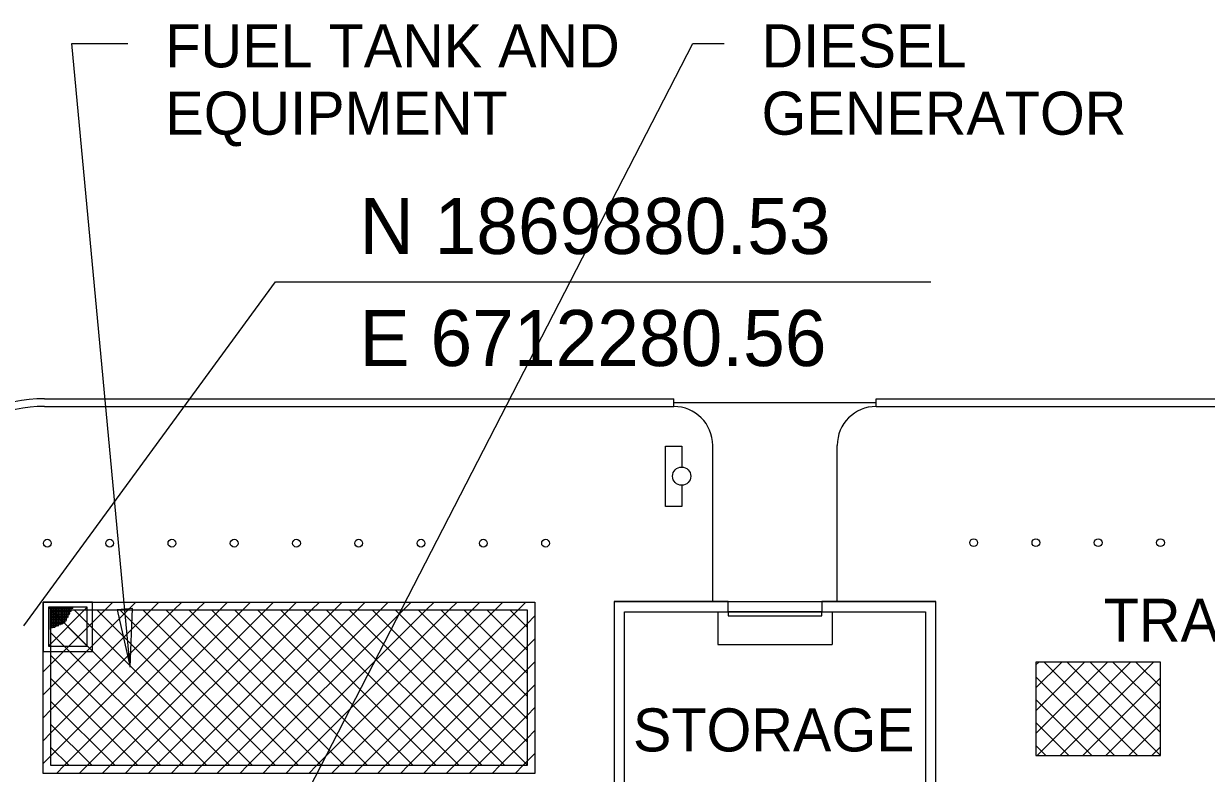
# Model space of a CAD drawing. Extents: x 6712138 to 6712574, y 1869536 to 1870160.
# Drawn here: x 6712280.5 to 6712356.5, y 1869871 to 1869919.2 of the extents above; entities that cross this region are included whole.
import ezdxf

# ---------------------------------------------------------------- set-up
doc = ezdxf.new("R2010")
doc.units = 0
for name, color, linetype in [('A-ANNO-TEXT', 7, 'Continuous'), ('A-DETL-GENF', 7, 'Continuous'), ('A-DETL-MBND', 7, 'Continuous'), ('C-PRKG-CONC', 7, 'Continuous'), ('C-PRKG-STRP', 7, 'Continuous'), ('C-SIGN-PARKING', 7, 'Continuous'), ('G-DETL-LW02', 7, 'Continuous'), ('I-FURN', 7, 'Continuous'), ('I-WALL', 7, 'Continuous'), ('M-Plan-Misc', 7, 'Continuous')]:
    doc.layers.add(name, color=color, linetype=linetype)

msp = doc.modelspace()

# ---------------------------------------------------------------- linework, layer by layer
at = {"layer": 'A-ANNO-TEXT'}
for p, q in [((6712283.645, 1869917.929), (6712287.243, 1869917.929)), ((6712287.387, 1869877.857), (6712283.645, 1869917.929)), ((6712283.645, 1869917.929), (6712287.243, 1869917.929)), ((6712287.387, 1869877.857), (6712283.645, 1869917.929)), ((6712293.94, 1869860.435), (6712323.513, 1869917.929)), ((6712293.94, 1869860.435), (6712323.513, 1869917.929)), ((6712323.513, 1869917.929), (6712325.537, 1869917.929)), ((6712323.513, 1869917.929), (6712325.537, 1869917.929)), ((6712287.53, 1869881.637), (6712286.547, 1869881.545)), ((6712287.53, 1869881.637), (6712286.547, 1869881.545)), ((6712287.53, 1869881.637), (6712286.547, 1869881.545)), ((6712287.53, 1869881.637), (6712286.547, 1869881.545)), ((6712286.547, 1869881.545), (6712287.387, 1869877.857)), ((6712286.547, 1869881.545), (6712287.387, 1869877.857)), ((6712286.547, 1869881.545), (6712287.387, 1869877.857)), ((6712286.547, 1869881.545), (6712287.387, 1869877.857)), ((6712287.387, 1869877.857), (6712287.53, 1869881.637)), ((6712287.387, 1869877.857), (6712287.53, 1869881.637)), ((6712287.387, 1869877.857), (6712287.53, 1869881.637)), ((6712287.387, 1869877.857), (6712287.53, 1869881.637))]:
    msp.add_line(p, q, dxfattribs=at)
at = {"layer": 'A-DETL-GENF'}
for p, q in [((6712282.297, 1869878.058), (6712285.778, 1869881.538)), ((6712282.297, 1869876.585), (6712287.251, 1869881.538)), ((6712282.297, 1869873.638), (6712290.197, 1869881.538)), ((6712282.297, 1869872.165), (6712291.671, 1869881.538)), ((6712282.297, 1869873.638), (6712290.197, 1869881.538)), ((6712282.297, 1869872.165), (6712291.671, 1869881.538)), ((6712282.297, 1869878.058), (6712285.778, 1869881.538)), ((6712282.297, 1869876.585), (6712287.251, 1869881.538)), ((6712282.297, 1869875.111), (6712288.724, 1869881.538)), ((6712292.304, 1869871.538), (6712282.304, 1869881.538)), ((6712283.144, 1869871.538), (6712293.144, 1869881.538)), ((6712283.144, 1869871.538), (6712293.144, 1869881.538)), ((6712293.777, 1869871.538), (6712283.777, 1869881.538)), ((6712284.617, 1869871.538), (6712294.617, 1869881.538)), ((6712284.617, 1869871.538), (6712294.617, 1869881.538)), ((6712295.25, 1869871.538), (6712285.25, 1869881.538)), ((6712285.778, 1869881.538), (6712286.278, 1869882.038)), ((6712286.09, 1869871.538), (6712296.09, 1869881.538)), ((6712286.09, 1869871.538), (6712296.09, 1869881.538)), ((6712296.723, 1869871.538), (6712286.723, 1869881.538)), ((6712287.251, 1869881.538), (6712287.751, 1869882.038)), ((6712287.563, 1869871.538), (6712297.563, 1869881.538)), ((6712287.563, 1869871.538), (6712297.563, 1869881.538)), ((6712298.196, 1869871.538), (6712288.196, 1869881.538)), ((6712288.724, 1869881.538), (6712289.224, 1869882.038)), ((6712289.036, 1869871.538), (6712299.036, 1869881.538)), ((6712289.036, 1869871.538), (6712299.036, 1869881.538)), ((6712299.67, 1869871.538), (6712289.67, 1869881.538)), ((6712290.197, 1869881.538), (6712290.697, 1869882.038)), ((6712290.509, 1869871.538), (6712300.509, 1869881.538)), ((6712290.509, 1869871.538), (6712300.509, 1869881.538)), ((6712301.143, 1869871.538), (6712291.143, 1869881.538)), ((6712291.671, 1869881.538), (6712292.171, 1869882.038)), ((6712291.983, 1869871.538), (6712301.983, 1869881.538)), ((6712291.983, 1869871.538), (6712301.983, 1869881.538)), ((6712302.616, 1869871.538), (6712292.616, 1869881.538)), ((6712293.144, 1869881.538), (6712293.644, 1869882.038)), ((6712293.456, 1869871.538), (6712303.456, 1869881.538)), ((6712293.456, 1869871.538), (6712303.456, 1869881.538)), ((6712304.089, 1869871.538), (6712294.089, 1869881.538)), ((6712294.617, 1869881.538), (6712295.117, 1869882.038)), ((6712294.929, 1869871.538), (6712304.929, 1869881.538)), ((6712294.929, 1869871.538), (6712304.929, 1869881.538)), ((6712305.562, 1869871.538), (6712295.562, 1869881.538)), ((6712296.09, 1869881.538), (6712296.59, 1869882.038)), ((6712296.402, 1869871.538), (6712306.402, 1869881.538)), ((6712296.402, 1869871.538), (6712306.402, 1869881.538)), ((6712307.035, 1869871.538), (6712297.035, 1869881.538)), ((6712297.563, 1869881.538), (6712298.063, 1869882.038)), ((6712297.875, 1869871.538), (6712307.875, 1869881.538)), ((6712297.875, 1869871.538), (6712307.875, 1869881.538)), ((6712308.508, 1869871.538), (6712298.508, 1869881.538)), ((6712299.036, 1869881.538), (6712299.536, 1869882.038)), ((6712299.348, 1869871.538), (6712309.348, 1869881.538)), ((6712299.348, 1869871.538), (6712309.348, 1869881.538)), ((6712309.981, 1869871.538), (6712299.981, 1869881.538)), ((6712300.509, 1869881.538), (6712301.009, 1869882.038)), ((6712300.821, 1869871.538), (6712310.821, 1869881.538)), ((6712300.821, 1869871.538), (6712310.821, 1869881.538)), ((6712311.455, 1869871.538), (6712301.455, 1869881.538)), ((6712301.983, 1869881.538), (6712302.483, 1869882.038)), ((6712302.295, 1869871.538), (6712312.295, 1869881.538)), ((6712302.295, 1869871.538), (6712312.295, 1869881.538)), ((6712312.881, 1869871.585), (6712302.928, 1869881.538)), ((6712303.456, 1869881.538), (6712303.956, 1869882.038)), ((6712312.881, 1869873.059), (6712304.401, 1869881.538)), ((6712304.929, 1869881.538), (6712305.429, 1869882.038)), ((6712312.881, 1869874.532), (6712305.874, 1869881.538)), ((6712306.402, 1869881.538), (6712306.902, 1869882.038)), ((6712312.881, 1869876.005), (6712307.347, 1869881.538)), ((6712307.875, 1869881.538), (6712308.375, 1869882.038)), ((6712312.881, 1869877.478), (6712308.82, 1869881.538)), ((6712309.348, 1869881.538), (6712309.848, 1869882.038)), ((6712312.881, 1869878.951), (6712310.293, 1869881.538)), ((6712310.821, 1869881.538), (6712311.321, 1869882.038)), ((6712312.881, 1869880.424), (6712311.767, 1869881.538)), ((6712312.295, 1869881.538), (6712312.795, 1869882.038)), ((6712318.464, 1869882.073), (6712318.464, 1869856.073)), ((6712325.797, 1869882.073), (6712318.464, 1869882.073)), ((6712319.131, 1869856.739), (6712319.131, 1869881.406)), ((6712319.131, 1869881.406), (6712325.797, 1869881.406)), ((6712325.797, 1869881.406), (6712325.797, 1869882.073)), ((6712339.131, 1869882.073), (6712331.797, 1869882.073)), ((6712331.797, 1869882.073), (6712331.797, 1869881.406)), ((6712331.797, 1869881.406), (6712338.464, 1869881.406)), ((6712338.464, 1869881.406), (6712338.464, 1869856.739)), ((6712339.131, 1869856.073), (6712339.131, 1869882.073)), ((6712303.768, 1869871.538), (6712312.881, 1869880.651)), ((6712303.768, 1869871.538), (6712312.881, 1869880.651)), ((6712312.881, 1869880.651), (6712313.381, 1869881.151)), ((6712290.831, 1869871.538), (6712282.297, 1869880.072)), ((6712305.241, 1869871.538), (6712312.881, 1869879.178)), ((6712305.241, 1869871.538), (6712312.881, 1869879.178)), ((6712312.881, 1869879.178), (6712313.381, 1869879.678)), ((6712289.358, 1869871.538), (6712282.297, 1869878.599)), ((6712281.797, 1869877.558), (6712282.297, 1869878.058)), ((6712306.714, 1869871.538), (6712312.881, 1869877.705)), ((6712312.881, 1869877.705), (6712313.381, 1869878.205)), ((6712345.557, 1869876.534), (6712347.212, 1869878.189)), ((6712345.557, 1869878.007), (6712345.739, 1869878.189)), ((6712345.557, 1869875.061), (6712348.685, 1869878.189)), ((6712345.557, 1869873.588), (6712350.158, 1869878.189)), ((6712345.631, 1869872.189), (6712351.631, 1869878.189)), ((6712352.086, 1869872.189), (6712346.086, 1869878.189)), ((6712347.105, 1869872.189), (6712353.105, 1869878.189)), ((6712347.105, 1869872.189), (6712353.105, 1869878.189)), ((6712353.557, 1869872.191), (6712347.56, 1869878.189)), ((6712353.557, 1869873.664), (6712349.033, 1869878.189)), ((6712353.557, 1869875.138), (6712350.506, 1869878.189)), ((6712353.557, 1869876.611), (6712351.979, 1869878.189)), ((6712287.884, 1869871.538), (6712282.297, 1869877.125)), ((6712350.613, 1869872.189), (6712345.557, 1869877.245)), ((6712348.578, 1869872.189), (6712353.557, 1869877.169)), ((6712281.797, 1869876.085), (6712282.297, 1869876.585)), ((6712308.187, 1869871.538), (6712312.881, 1869876.232)), ((6712312.881, 1869876.232), (6712313.381, 1869876.732)), ((6712286.411, 1869871.538), (6712282.297, 1869875.652)), ((6712349.14, 1869872.189), (6712345.557, 1869875.772)), ((6712349.14, 1869872.189), (6712345.557, 1869875.772)), ((6712350.051, 1869872.189), (6712353.557, 1869875.695)), ((6712281.797, 1869874.611), (6712282.297, 1869875.111)), ((6712309.66, 1869871.538), (6712312.881, 1869874.759)), ((6712312.881, 1869874.759), (6712313.381, 1869875.259)), ((6712284.938, 1869871.538), (6712282.297, 1869874.179)), ((6712312.881, 1869873.286), (6712313.381, 1869873.786)), ((6712347.667, 1869872.189), (6712345.557, 1869874.299)), ((6712351.524, 1869872.189), (6712353.557, 1869874.222)), ((6712281.797, 1869873.138), (6712282.297, 1869873.638)), ((6712311.133, 1869871.538), (6712312.881, 1869873.286)), ((6712283.465, 1869871.538), (6712282.297, 1869872.706)), ((6712312.881, 1869871.813), (6712313.381, 1869872.313)), ((6712346.194, 1869872.189), (6712345.557, 1869872.826)), ((6712352.997, 1869872.189), (6712353.557, 1869872.749)), ((6712281.797, 1869871.665), (6712282.297, 1869872.165)), ((6712282.644, 1869871.038), (6712283.144, 1869871.538)), ((6712282.644, 1869871.038), (6712283.144, 1869871.538)), ((6712284.117, 1869871.038), (6712284.617, 1869871.538)), ((6712284.117, 1869871.038), (6712284.617, 1869871.538)), ((6712285.59, 1869871.038), (6712286.09, 1869871.538)), ((6712285.59, 1869871.038), (6712286.09, 1869871.538)), ((6712287.063, 1869871.038), (6712287.563, 1869871.538)), ((6712287.063, 1869871.038), (6712287.563, 1869871.538)), ((6712288.536, 1869871.038), (6712289.036, 1869871.538)), ((6712288.536, 1869871.038), (6712289.036, 1869871.538)), ((6712290.009, 1869871.038), (6712290.509, 1869871.538)), ((6712290.009, 1869871.038), (6712290.509, 1869871.538)), ((6712291.483, 1869871.038), (6712291.983, 1869871.538)), ((6712291.483, 1869871.038), (6712291.983, 1869871.538)), ((6712292.956, 1869871.038), (6712293.456, 1869871.538)), ((6712292.956, 1869871.038), (6712293.456, 1869871.538)), ((6712294.429, 1869871.038), (6712294.929, 1869871.538)), ((6712294.429, 1869871.038), (6712294.929, 1869871.538)), ((6712295.902, 1869871.038), (6712296.402, 1869871.538)), ((6712295.902, 1869871.038), (6712296.402, 1869871.538)), ((6712297.375, 1869871.038), (6712297.875, 1869871.538)), ((6712297.375, 1869871.038), (6712297.875, 1869871.538)), ((6712298.848, 1869871.038), (6712299.348, 1869871.538)), ((6712298.848, 1869871.038), (6712299.348, 1869871.538)), ((6712300.321, 1869871.038), (6712300.821, 1869871.538)), ((6712300.321, 1869871.038), (6712300.821, 1869871.538)), ((6712301.795, 1869871.038), (6712302.295, 1869871.538)), ((6712301.795, 1869871.038), (6712302.295, 1869871.538)), ((6712303.268, 1869871.038), (6712303.768, 1869871.538)), ((6712303.268, 1869871.038), (6712303.768, 1869871.538)), ((6712304.741, 1869871.038), (6712305.241, 1869871.538)), ((6712304.741, 1869871.038), (6712305.241, 1869871.538)), ((6712306.214, 1869871.038), (6712306.714, 1869871.538)), ((6712306.214, 1869871.038), (6712306.714, 1869871.538)), ((6712307.687, 1869871.038), (6712308.187, 1869871.538)), ((6712307.687, 1869871.038), (6712308.187, 1869871.538)), ((6712309.16, 1869871.038), (6712309.66, 1869871.538)), ((6712309.16, 1869871.038), (6712309.66, 1869871.538)), ((6712310.633, 1869871.038), (6712311.133, 1869871.538)), ((6712310.633, 1869871.038), (6712311.133, 1869871.538)), ((6712312.106, 1869871.038), (6712312.606, 1869871.538)), ((6712312.106, 1869871.038), (6712312.606, 1869871.538)), ((6712312.606, 1869871.538), (6712312.881, 1869871.813))]:
    msp.add_line(p, q, dxfattribs=at)
at = {"layer": 'A-DETL-MBND'}
for p, q in [((6712325.131, 1869881.406), (6712325.131, 1869879.323)), ((6712325.131, 1869881.406), (6712332.464, 1869881.406)), ((6712331.797, 1869881.406), (6712325.797, 1869881.406)), ((6712325.797, 1869881.406), (6712325.797, 1869881.156)), ((6712331.797, 1869881.156), (6712331.797, 1869881.406)), ((6712332.464, 1869881.406), (6712332.464, 1869879.323)), ((6712325.797, 1869881.156), (6712331.797, 1869881.156)), ((6712325.131, 1869879.323), (6712332.464, 1869879.323))]:
    msp.add_line(p, q, dxfattribs=at)
at = {"layer": 'C-PRKG-CONC'}
for p, q in [((6712281.89, 1869895.107), (6712322.297, 1869895.107)), ((6712322.297, 1869894.607), (6712322.297, 1869895.107)), ((6712335.297, 1869894.607), (6712335.297, 1869895.107)), ((6712335.297, 1869895.107), (6712372.34, 1869895.107)), ((6712281.89, 1869894.607), (6712322.297, 1869894.607)), ((6712322.297, 1869894.857), (6712335.297, 1869894.857)), ((6712335.297, 1869894.607), (6712372.34, 1869894.607)), ((6712324.797, 1869882.073), (6712324.797, 1869892.107)), ((6712324.797, 1869882.073), (6712324.797, 1869892.074)), ((6712332.797, 1869882.074), (6712332.797, 1869892.107)), ((6712332.797, 1869882.074), (6712332.797, 1869892.074))]:
    msp.add_line(p, q, dxfattribs=at)
for centre, radius, start, end in [((6712281.89, 1869885.107), 10, 90, 180.00085), ((6712281.89, 1869885.107), 9.5, 90, 180.00085), ((6712322.297, 1869892.107), 2.5, 0, 90), ((6712335.297, 1869892.107), 2.5, 90, 180)]:
    msp.add_arc(centre, radius, start, end, dxfattribs=at)
at = {"layer": 'C-PRKG-STRP'}
msp.add_line((6712318.464, 1869882.073), (6712339.131, 1869882.073), dxfattribs=at)
at = {"layer": 'C-SIGN-PARKING'}
msp.add_lwpolyline([(6712322.807, 1869889.542), (6712322.807, 1869888.19), (6712321.773, 1869888.19), (6712321.773, 1869892.066), (6712322.807, 1869892.066), (6712322.807, 1869890.714)], dxfattribs=at)
msp.add_circle((6712322.807, 1869890.128), 0.586, dxfattribs=at)
at = {"layer": 'G-DETL-LW02'}
for points in [[(6712281.797, 1869882.038), (6712313.381, 1869882.038), (6712313.381, 1869871.038), (6712281.797, 1869871.038)], [(6712282.297, 1869881.538), (6712312.881, 1869881.538), (6712312.881, 1869871.538), (6712282.297, 1869871.538)], [(6712345.557, 1869878.189), (6712345.557, 1869872.189), (6712353.557, 1869872.189), (6712353.557, 1869878.189)]]:
    msp.add_lwpolyline(points, close=True, dxfattribs=at)
at = {"layer": 'I-FURN'}
for centre in [(6712282.064, 1869885.823), (6712286.064, 1869885.823), (6712290.064, 1869885.823), (6712294.064, 1869885.823), (6712298.064, 1869885.823), (6712302.064, 1869885.823), (6712306.064, 1869885.823), (6712310.064, 1869885.823), (6712314.064, 1869885.823), (6712341.557, 1869885.857), (6712345.557, 1869885.857), (6712349.557, 1869885.857), (6712353.557, 1869885.857)]:
    msp.add_circle(centre, 0.25, dxfattribs=at)
at = {"layer": 'I-WALL'}
for points in [[(6712280.558, 1869880.525), (6712296.723, 1869902.604)], [(6712296.723, 1869902.604), (6712338.804, 1869902.604)]]:
    msp.add_lwpolyline(points, dxfattribs=at)
at = {"layer": 'M-Plan-Misc'}
for p, q in [((6712284.631, 1869881.705), (6712282.131, 1869879.205)), ((6712282.131, 1869881.705), (6712284.631, 1869879.205)), ((6712282.223, 1869881.652), (6712283.691, 1869881.652)), ((6712282.223, 1869881.55), (6712283.63, 1869881.55)), ((6712282.223, 1869881.449), (6712283.578, 1869881.449)), ((6712282.253, 1869881.688), (6712282.253, 1869880.315)), ((6712282.354, 1869881.688), (6712282.354, 1869880.356)), ((6712282.456, 1869881.688), (6712282.456, 1869880.398)), ((6712282.557, 1869881.688), (6712282.557, 1869880.439)), ((6712282.659, 1869881.688), (6712282.659, 1869880.481)), ((6712282.76, 1869881.688), (6712282.76, 1869880.522)), ((6712282.862, 1869881.688), (6712282.862, 1869880.564)), ((6712282.964, 1869881.688), (6712282.964, 1869880.605)), ((6712283.065, 1869881.688), (6712283.065, 1869880.646)), ((6712283.167, 1869881.688), (6712283.167, 1869880.688)), ((6712283.268, 1869881.688), (6712283.268, 1869880.851)), ((6712283.37, 1869881.688), (6712283.37, 1869881.047)), ((6712283.471, 1869881.688), (6712283.471, 1869881.243)), ((6712283.573, 1869881.688), (6712283.573, 1869881.439)), ((6712283.675, 1869881.688), (6712283.675, 1869881.636)), ((6712282.223, 1869881.347), (6712283.525, 1869881.347)), ((6712282.223, 1869881.246), (6712283.473, 1869881.246)), ((6712282.223, 1869881.144), (6712283.42, 1869881.144)), ((6712282.223, 1869881.042), (6712283.368, 1869881.042)), ((6712282.223, 1869880.941), (6712283.315, 1869880.941)), ((6712282.223, 1869880.839), (6712283.262, 1869880.839)), ((6712282.223, 1869880.738), (6712283.21, 1869880.738)), ((6712282.223, 1869880.636), (6712283.04, 1869880.636)), ((6712282.223, 1869880.535), (6712282.791, 1869880.535)), ((6712282.223, 1869880.433), (6712282.542, 1869880.433)), ((6712282.223, 1869880.332), (6712282.293, 1869880.332))]:
    msp.add_line(p, q, dxfattribs=at)
for points in [[(6712281.797, 1869882.038), (6712281.797, 1869878.872), (6712284.964, 1869878.872), (6712284.964, 1869882.038)], [(6712282.131, 1869881.705), (6712282.131, 1869879.205), (6712284.631, 1869879.205), (6712284.631, 1869881.705)]]:
    msp.add_lwpolyline(points, close=True, dxfattribs=at)

# ---------------------------------------------------------------- texts
at = {"layer": 'A-ANNO-TEXT'}
for s, height, p in [('FUEL TANK AND', 2.76619, (6712289.643, 1869916.393)), ('FUEL TANK AND', 2.76619, (6712289.643, 1869916.393)), ('DIESEL', 2.7662, (6712327.937, 1869916.393)), ('DIESEL', 2.7662, (6712327.937, 1869916.393)), ('EQUIPMENT', 2.7662, (6712289.643, 1869912.066)), ('EQUIPMENT', 2.7662, (6712289.643, 1869912.066)), ('GENERATOR', 2.7662, (6712327.937, 1869912.066)), ('GENERATOR', 2.7662, (6712327.937, 1869912.066)), ('TRANSFORMERS', 2.76619, (6712349.916, 1869879.492)), ('TRANSFORMERS', 2.76619, (6712349.916, 1869879.492)), ('STORAGE', 2.7662, (6712319.676, 1869872.446)), ('STORAGE', 2.7662, (6712319.676, 1869872.446))]:
    msp.add_text(s, height=height, dxfattribs=at).set_placement(p)
at = {"layer": 'I-WALL'}
for s, p in [('N 1869880.53', (6712302.123, 1869904.404)), ('E 6712280.56', (6712302.123, 1869897.204))]:
    msp.add_text(s, height=3.6, dxfattribs=at).set_placement(p)

doc.saveas('drawing.dxf')
